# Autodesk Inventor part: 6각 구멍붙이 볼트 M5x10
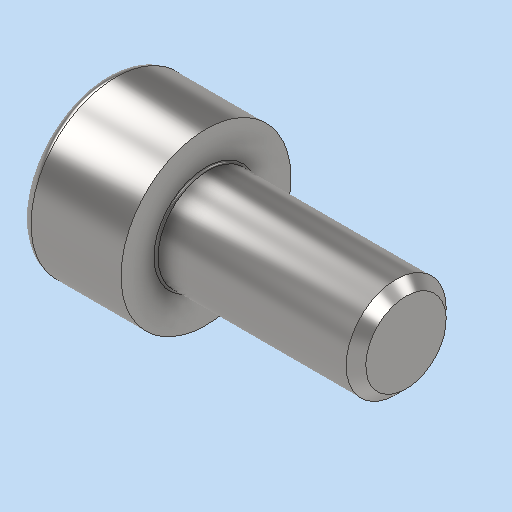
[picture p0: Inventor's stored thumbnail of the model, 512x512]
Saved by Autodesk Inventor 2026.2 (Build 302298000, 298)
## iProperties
Created: 2026-01
Part Number: 6각 구멍붙이 볼트 M5x10
Material: 강철, 연강
Description: 6각머리 태핑 나사
Document SubType Name: Modeling
Designer: PC2-07
Density: 7.85 g/cm^3
Appearance: 기본값
Author: jhkim
Sending System: Autodesk Inventor 2026
Preprocessor: ST-DEVELOPER v20.1
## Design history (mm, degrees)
feature "Solid1"
node "솔리드1"
